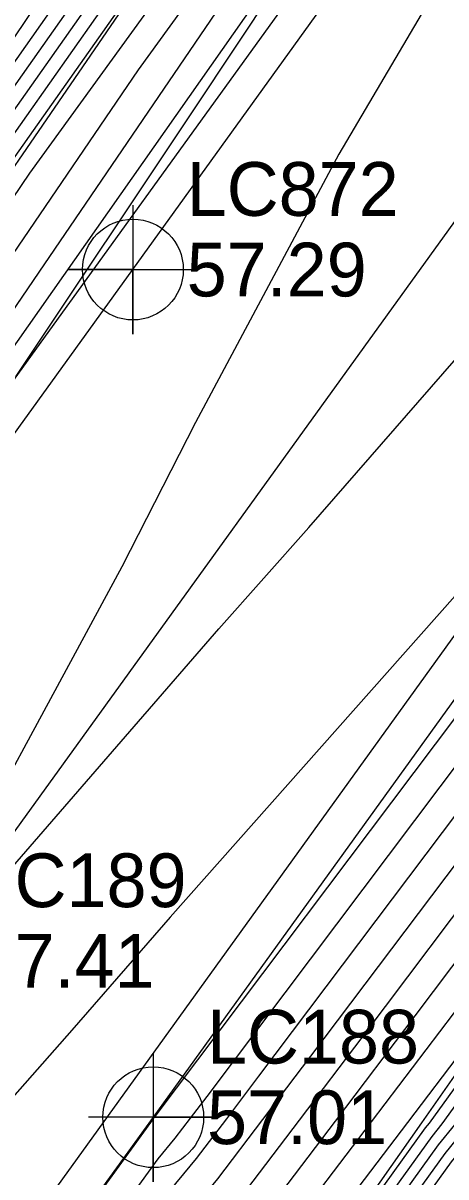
# Model space of a CAD drawing. Extents: x 2188792 to 2191981, y 386090 to 389710.
# Drawn here: x 2190120 to 2190139.6, y 387575.7 to 387629.4 of the extents above; entities that cross this region are included whole.
import ezdxf

# ---------------------------------------------------------------- set-up
doc = ezdxf.new("R2010")
doc.units = 0
for name, color, linetype in [('DTM Contours Major', 7, 'Continuous'), ('DTM Contours Minor', 7, 'Continuous'), ('Exist DTM Breakline', 7, 'Continuous'), ('Exist Roads EOP', 7, 'Continuous'), ('Exist Roads EOP Cogo Elevation', 7, 'Continuous'), ('Exist Roads EOP Cogo Number', 7, 'Continuous'), ('Exist Roads EOP Cogo Point CELL', 7, 'Continuous'), ('Exist Roads EOT', 7, 'Continuous'), ('Exist Roads EOT Cogo Elevation', 7, 'Continuous'), ('Exist Roads EOT Cogo Number', 7, 'Continuous'), ('Exist Roads EOT Cogo Point CELL', 7, 'Continuous'), ('PH Exist DTM Breakline', 7, 'Continuous')]:
    doc.layers.add(name, color=color, linetype=linetype)

msp = doc.modelspace()

# ---------------------------------------------------------------- linework, layer by layer
at = {"layer": 'DTM Contours Major'}
for points in [[(2190083.158, 387573.776), (2190093.446, 387588.169), (2190099.389, 387596.314), (2190111.555, 387613.65), (2190116.478, 387620.96), (2190126.328, 387634.955), (2190130.014, 387640.455), (2190140.89, 387656.284), (2190146.901, 387665.291)], [(2190151.311, 387661.898), (2190146.496, 387654.704), (2190134.166, 387637.26), (2190130.399, 387632.051), (2190120.729, 387617.824), (2190106.225, 387596.486), (2190103.722, 387593.114), (2190101.482, 387589.813), (2190086.86, 387570.121)], [(2190091.393, 387530.607), (2190108.388, 387554.062), (2190108.431, 387554.123), (2190108.48, 387554.184), (2190108.533, 387554.249), (2190108.59, 387554.318), (2190126.056, 387578.434), (2190126.083, 387578.467), (2190126.108, 387578.499), (2190126.134, 387578.534), (2190140.156, 387597.174), (2190140.433, 387597.539), (2190140.728, 387597.929), (2190141.045, 387598.361), (2190157.562, 387620.323), (2190158.167, 387621.152), (2190158.815, 387622.039), (2190167.49, 387633.85), (2190168.237, 387634.874), (2190169.128, 387635.987), (2190170.079, 387637.175), (2190184.662, 387656.987)], [(2190177.393, 387635.531), (2190172.172, 387629.008), (2190167.794, 387623.009), (2190166.39, 387621.099), (2190162.031, 387615.129), (2190157.956, 387609.549), (2190154.257, 387604.63), (2190150.045, 387598.88), (2190146.112, 387593.69), (2190142.422, 387588.822), (2190138.204, 387583.214), (2190134.502, 387578.326), (2190131.026, 387573.736), (2190127.204, 387569.116), (2190120.791, 387560.26), (2190116.838, 387555.416), (2190113.147, 387550.892), (2190109.69, 387546.656), (2190106.731, 387542.448), (2190099.469, 387532.426)], [(2190179.508, 387633.984), (2190175.468, 387628.708), (2190173.93, 387626.854), (2190170.242, 387621.521), (2190169.204, 387620.33), (2190168.295, 387618.819), (2190164.392, 387613.172), (2190163.521, 387611.703), (2190159.485, 387605.874), (2190158.87, 387604.781), (2190154.769, 387598.87), (2190154.188, 387597.838), (2190150.022, 387592.055), (2190149.476, 387591.084), (2190145.243, 387585.22), (2190144.371, 387584.145), (2190140.055, 387578.156), (2190139.296, 387577.214), (2190134.904, 387571.112)]]:
    msp.add_lwpolyline(points, dxfattribs=at)
at = {"layer": 'DTM Contours Minor'}
for points in [[(2190065.514, 387514.559), (2190081.303, 387536.264), (2190082.63, 387538.282), (2190097.61, 387559.851), (2190098.692, 387561.489), (2190115.183, 387585.188), (2190115.572, 387585.629), (2190129.097, 387601.222), (2190133.281, 387605.947), (2190145.736, 387620.245), (2190151.288, 387627.466), (2190156.609, 387634.62), (2190165.07, 387645.609), (2190174.107, 387657.741), (2190181.981, 387667.906), (2190187.788, 387675.299), (2190199.057, 387689.861), (2190205.414, 387697.968), (2190216.141, 387711.606), (2190219.575, 387716.076), (2190234.549, 387735.079)], [(2190086.373, 387581.355), (2190098.113, 387597.446), (2190104.166, 387606.071), (2190115.056, 387622.241), (2190119.115, 387628.008), (2190128.334, 387641.763), (2190131.832, 387646.855), (2190145.085, 387666.714)], [(2190088.731, 387583.626), (2190098.538, 387597.069), (2190106.629, 387608.597), (2190115.53, 387621.814), (2190121.519, 387630.323), (2190128.894, 387641.327), (2190134.852, 387649.998), (2190145.69, 387666.24)], [(2190082.705, 387574.169), (2190091.088, 387585.898), (2190098.963, 387596.692), (2190109.092, 387611.124), (2190116.004, 387621.387), (2190123.924, 387632.639), (2190129.454, 387640.891), (2190137.871, 387653.141), (2190146.296, 387665.766)], [(2190148.998, 387663.661), (2190136.26, 387644.629), (2190132.146, 387638.808), (2190120.301, 387622.428), (2190118.291, 387619.471), (2190115.277, 387615.037), (2190102.817, 387598.25), (2190100.664, 387595.183), (2190100.519, 387594.984), (2190098.32, 387591.907), (2190087.424, 387575.855)], [(2190146.929, 387662.57), (2190131.187, 387639.658), (2190131.142, 387639.591), (2190131.136, 387639.582), (2190131.092, 387639.521), (2190117.426, 387620.106), (2190116.481, 387618.702), (2190100.239, 387595.56), (2190098.161, 387592.713), (2190084.065, 387572.99)], [(2190150.155, 387662.779), (2190141.378, 387649.667), (2190133.156, 387638.034), (2190125.35, 387627.24), (2190119.51, 387618.648), (2190110.751, 387605.761), (2190102.15, 387594.174), (2190094.453, 387582.834), (2190085.819, 387571.206)], [(2190084.006, 387557.4), (2190094.856, 387571.695), (2190099.134, 387577.453), (2190107.444, 387593.46), (2190110.09, 387597.703), (2190119.651, 387612.941), (2190119.659, 387612.954), (2190119.678, 387612.982), (2190128.004, 387625.475), (2190135.398, 387636.642), (2190136.43, 387638.136), (2190139.311, 387642.336), (2190151.615, 387659.742)], [(2190184.837, 387659.663), (2190167.502, 387636.111), (2190167.475, 387636.078), (2190167.45, 387636.047), (2190167.429, 387636.018), (2190165.598, 387633.525), (2190156.429, 387623.349), (2190154.429, 387620.887), (2190143.422, 387606.569), (2190142.383, 387605.376), (2190126.829, 387587.81), (2190122.267, 387582.551), (2190113.856, 387573.015), (2190106.443, 387562.363), (2190096.147, 387546.786), (2190090.433, 387538.558)], [(2190083.612, 387573.383), (2190095.804, 387590.441), (2190099.814, 387595.937), (2190114.018, 387616.176), (2190116.952, 387620.533), (2190128.733, 387637.271), (2190130.575, 387640.019), (2190143.91, 387659.427)], [(2190094.623, 387531.335), (2190107.725, 387549.417), (2190108.935, 387551.136), (2190110.347, 387552.867), (2190111.855, 387554.716), (2190113.47, 387556.695), (2190126.515, 387574.707), (2190128.06, 387576.575), (2190129.465, 387578.43), (2190130.962, 387580.406), (2190141.062, 387593.833), (2190142.704, 387596), (2190144.455, 387598.31), (2190146.33, 387600.869), (2190157.72, 387616.014), (2190159.713, 387618.743), (2190161.845, 387621.663), (2190167.611, 387629.514), (2190169.811, 387632.527), (2190172.434, 387635.805), (2190175.234, 387639.303), (2190184.312, 387651.637), (2190187.135, 387655.131), (2190190.153, 387658.866)], [(2190155.266, 387658.13), (2190146.358, 387642.623), (2190143.945, 387639.083), (2190134.669, 387623.313), (2190128.018, 387610.831), (2190124.584, 387604.112), (2190115.056, 387586.462), (2190114.502, 387585.393), (2190097.474, 387562.47), (2190096.333, 387560.967), (2190081.138, 387540.528)], [(2190096.239, 387531.699), (2190107.394, 387547.094), (2190109.187, 387549.643), (2190111.28, 387552.209), (2190113.516, 387554.949), (2190115.911, 387557.883), (2190126.745, 387572.843), (2190129.049, 387575.628), (2190131.144, 387578.395), (2190133.376, 387581.342), (2190141.516, 387592.162), (2190143.84, 387595.23), (2190146.318, 387598.5), (2190148.972, 387602.122), (2190157.799, 387613.859), (2190160.485, 387617.538), (2190163.36, 387621.475), (2190167.672, 387627.346), (2190170.598, 387631.354), (2190174.087, 387635.713), (2190177.811, 387640.367), (2190184.137, 387648.961), (2190187.814, 387653.513), (2190191.746, 387658.38)], [(2190193.339, 387657.893), (2190188.494, 387651.895), (2190183.962, 387646.286), (2190180.388, 387641.431), (2190175.74, 387635.622), (2190171.385, 387630.181), (2190167.733, 387625.177), (2190164.875, 387621.287), (2190161.258, 387616.333), (2190157.877, 387611.704), (2190151.614, 387603.376), (2190148.181, 387598.69), (2190144.976, 387594.46), (2190141.969, 387590.492), (2190135.79, 387582.278), (2190132.823, 387578.36), (2190130.037, 387574.682), (2190126.975, 387570.98), (2190118.351, 387559.072), (2190115.177, 387555.183), (2190112.213, 387551.55), (2190109.438, 387548.149), (2190107.063, 387544.771), (2190097.854, 387532.062)], [(2190093.008, 387530.971), (2190108.057, 387551.739), (2190108.683, 387552.629), (2190109.414, 387553.525), (2190110.194, 387554.482), (2190111.03, 387555.507), (2190126.286, 387576.571), (2190127.072, 387577.521), (2190127.786, 387578.465), (2190128.548, 387579.47), (2190140.609, 387595.503), (2190141.569, 387596.769), (2190142.592, 387598.119), (2190143.687, 387599.615), (2190157.641, 387618.168), (2190158.94, 387619.948), (2190160.33, 387621.851), (2190167.551, 387631.682), (2190169.024, 387633.701), (2190170.781, 387635.896), (2190172.656, 387638.239), (2190184.487, 387654.312), (2190186.455, 387656.748)], [(2190178.377, 387635.321), (2190172.918, 387628.192), (2190172.819, 387628.073), (2190167.873, 387620.922), (2190167.864, 387620.912), (2190167.856, 387620.899), (2190167.133, 387619.852), (2190162.804, 387613.924), (2190158.035, 387607.394), (2190156.899, 387605.883), (2190151.908, 387599.07), (2190147.247, 387592.92), (2190142.876, 387587.151), (2190140.618, 387584.151), (2190136.181, 387578.291), (2190132.014, 387572.79), (2190127.434, 387567.252), (2190123.231, 387561.449), (2190118.499, 387555.65), (2190114.08, 387550.234), (2190109.942, 387545.163), (2190106.4, 387540.126), (2190101.085, 387532.79)], [(2190178.66, 387634.987), (2190173.555, 387628.321), (2190173.097, 387627.768), (2190168.465, 387621.072), (2190168.199, 387620.767), (2190167.966, 387620.379), (2190163.261, 387613.572), (2190163.079, 387613.264), (2190158.292, 387606.35), (2190158.195, 387606.179), (2190153.332, 387599.168), (2190153.276, 387599.069), (2190148.335, 387592.21), (2190148.321, 387592.184), (2190146.552, 387589.734), (2190143.329, 387585.481), (2190143.033, 387585.087), (2190137.859, 387578.256), (2190133.003, 387571.844)], [(2190178.942, 387634.653), (2190174.193, 387628.45), (2190173.375, 387627.463), (2190169.057, 387621.222), (2190168.534, 387620.621), (2190168.076, 387619.859), (2190163.638, 387613.439), (2190163.226, 387612.744), (2190158.69, 387606.192), (2190158.42, 387605.713), (2190153.811, 387599.069), (2190153.58, 387598.659), (2190148.898, 387592.158), (2190148.706, 387591.817), (2190143.947, 387585.226), (2190143.688, 387584.905), (2190138.871, 387578.222), (2190138.692, 387578.001), (2190133.822, 387571.234)], [(2190179.225, 387634.318), (2190174.83, 387628.579), (2190173.653, 387627.158), (2190169.649, 387621.371), (2190168.869, 387620.476), (2190168.186, 387619.339), (2190164.015, 387613.305), (2190163.374, 387612.223), (2190159.087, 387606.033), (2190158.645, 387605.247), (2190154.29, 387598.969), (2190153.884, 387598.249), (2190149.46, 387592.106), (2190149.091, 387591.451), (2190144.595, 387585.223), (2190144.029, 387584.525), (2190139.463, 387578.189), (2190138.994, 387577.608), (2190134.363, 387571.173)], [(2190179.791, 387633.65), (2190176.105, 387628.837), (2190174.208, 387626.549), (2190170.834, 387621.671), (2190169.539, 387620.185), (2190168.405, 387618.299), (2190164.77, 387613.039), (2190163.669, 387611.183), (2190159.883, 387605.715), (2190159.095, 387604.315), (2190155.248, 387598.771), (2190154.492, 387597.428), (2190150.585, 387592.003), (2190149.861, 387590.718), (2190145.89, 387585.218), (2190144.712, 387583.764), (2190140.646, 387578.123), (2190139.597, 387576.821), (2190135.445, 387571.052)], [(2190176.743, 387628.965), (2190174.486, 387626.244), (2190171.426, 387621.821), (2190169.874, 387620.039), (2190168.515, 387617.78), (2190165.147, 387612.906), (2190163.816, 387610.662), (2190160.281, 387605.556), (2190159.319, 387603.849), (2190155.727, 387598.671), (2190154.796, 387597.018), (2190151.147, 387591.951), (2190150.246, 387590.351), (2190146.538, 387585.215), (2190145.054, 387583.384), (2190141.238, 387578.09), (2190139.899, 387576.428), (2190135.986, 387570.991)]]:
    msp.add_lwpolyline(points, dxfattribs=at)
at = {"layer": 'Exist DTM Breakline'}
for points in [[(2189995.924, 387449.921), (2190033.109, 387498.748), (2190066.603, 387548.559), (2190100.696, 387595.155), (2190131.134, 387639.583), (2190163.791, 387685.951), (2190192.781, 387722.608)], [(2189998.889, 387447.645), (2190035.636, 387497.082), (2190069.466, 387545.534), (2190104.367, 387592.678), (2190135.108, 387636.538), (2190168.392, 387682.449), (2190194.386, 387718.656)]]:
    msp.add_lwpolyline(points, dxfattribs=at)
at = {"layer": 'Exist Roads EOP'}
for points in [[(2190313.986, 387884.141), (2190285.547, 387843.636), (2190254.588, 387800.045), (2190225.155, 387759.32), (2190194.829, 387717.425), (2190164.291, 387675.101), (2190137.229, 387637.301), (2190105.098, 387592.774), (2190071.411, 387546.221), (2190039.296, 387501.568), (2190007.542, 387457.958), (2189976.844, 387415.407), (2189936.359, 387359.145), (2189907.138, 387318.716), (2189868.636, 387265.243), (2189836.428, 387220.463), (2189805.695, 387177.815), (2189775.592, 387135.957), (2189745.498, 387094.055), (2189715.496, 387052.249), (2189683.869, 387008.07), (2189653.218, 386965.867), (2189623.729, 386924.667)], [(2190335.128, 387868.989), (2190306.373, 387829.271), (2190274.581, 387784.921), (2190245.133, 387744.071), (2190214.553, 387701.741), (2190184.89, 387660.475), (2190157.493, 387622.204), (2190126.048, 387578.501), (2190091.216, 387530.568), (2190059.634, 387486.726), (2190026.932, 387441.783), (2189997.689, 387401.032), (2189957.023, 387344.154), (2189927.908, 387303.922), (2189889.008, 387250.224), (2189856.606, 387205.5), (2189825.68, 387162.612), (2189795.668, 387120.822), (2189765.955, 387079.619), (2189734.998, 387036.704), (2189703.849, 386993.356), (2189673.984, 386951.979), (2189643.253, 386909.427)]]:
    msp.add_lwpolyline(points, dxfattribs=at)
at = {"layer": 'Exist Roads EOP Cogo Point CELL'}
msp.add_lwpolyline([(2190126.048, 387581.501), (2190126.048, 387575.501), (2190126.048, 387578.501), (2190129.048, 387578.501), (2190123.048, 387578.501)], dxfattribs=at)
msp.add_circle((2190126.048, 387578.501), 2.344, dxfattribs=at)
at = {"layer": 'Exist Roads EOT'}
for points in [[(2189910.407, 387320.236), (2189942.075, 387364.22), (2189970.438, 387403.768), (2190000.916, 387446.161), (2190032.053, 387489.248), (2190063.107, 387532.142), (2190093.978, 387574.79), (2190125.104, 387617.946), (2190155.102, 387659.638), (2190185.949, 387702.484), (2190216.886, 387745.11), (2190247.602, 387787.3), (2190276.876, 387828.015), (2190303.928, 387865.67), (2190323.039, 387892.195)], [(2190333.162, 387868.755), (2190301.785, 387825.12), (2190269.645, 387780.315), (2190237.827, 387736.49), (2190205.816, 387692.275), (2190173.845, 387647.822), (2190143.211, 387605.324), (2190112.772, 387563.076), (2190082.117, 387520.492), (2190050.947, 387477.405), (2190019.959, 387434.524), (2189989.253, 387391.986)], [(2190174.375, 387667.889), (2190147.471, 387630.495), (2190115.247, 387585.778), (2190081.202, 387538.232), (2190049.502, 387494.256), (2190017.538, 387450.182), (2189987.334, 387408.357), (2189946.666, 387352.019), (2189917.402, 387311.129), (2189878.955, 387257.772), (2189846.565, 387212.819), (2189815.837, 387170.306), (2189785.374, 387128.351), (2189755.717, 387086.921), (2189724.953, 387044.041), (2189693.727, 387000.805), (2189663.933, 386959.217), (2189633.425, 386917.196)]]:
    msp.add_lwpolyline(points, dxfattribs=at)
at = {"layer": 'Exist Roads EOT Cogo Point CELL'}
msp.add_lwpolyline([(2190125.104, 387620.946), (2190125.104, 387614.946), (2190125.104, 387617.946), (2190122.104, 387617.946), (2190128.104, 387617.946)], dxfattribs=at)
msp.add_circle((2190125.104, 387617.946), 2.344, dxfattribs=at)
at = {"layer": 'PH Exist DTM Breakline'}
msp.add_lwpolyline([(2190172.743, 387628.156), (2190167.852, 387620.917), (2190162.961, 387613.678), (2190158.07, 387606.439), (2190153.179, 387599.2), (2190148.288, 387592.214), (2190143.398, 387585.228), (2190138.507, 387578.243), (2190133.616, 387571.257), (2190127.871, 387563.708), (2190122.125, 387556.16), (2190116.38, 387548.611), (2190110.634, 387541.063), (2190105.495, 387533.783), (2190100.357, 387526.504), (2190095.218, 387519.224)], dxfattribs=at)

# ---------------------------------------------------------------- texts
at = {"layer": 'Exist Roads EOP Cogo Elevation'}
msp.add_text('57.01', height=2.5, dxfattribs=at).set_placement((2190128.548, 387577.251))
at = {"layer": 'Exist Roads EOP Cogo Number'}
msp.add_text('LC188', height=2.5, dxfattribs=at).set_placement((2190128.548, 387581.001))
at = {"layer": 'Exist Roads EOT Cogo Elevation'}
for s, p in [('57.29', (2190127.604, 387616.696)), ('57.41', (2190117.747, 387584.528))]:
    msp.add_text(s, height=2.5, dxfattribs=at).set_placement(p)
at = {"layer": 'Exist Roads EOT Cogo Number'}
for s, p in [('LC872', (2190127.604, 387620.446)), ('LC189', (2190117.747, 387588.278))]:
    msp.add_text(s, height=2.5, dxfattribs=at).set_placement(p)

doc.saveas('drawing.dxf')
